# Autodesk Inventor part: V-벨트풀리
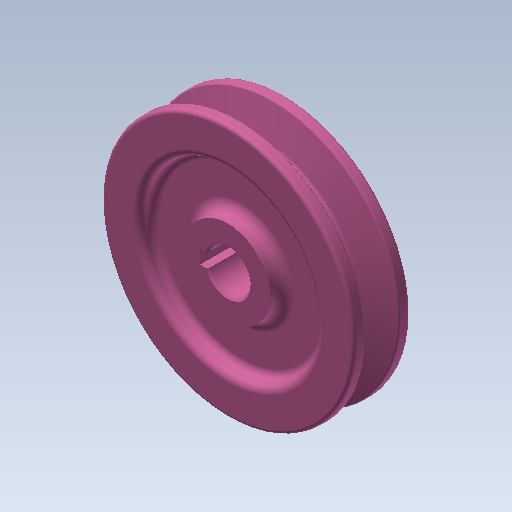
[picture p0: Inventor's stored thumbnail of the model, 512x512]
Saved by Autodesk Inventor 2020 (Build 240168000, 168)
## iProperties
CustomPartVersion: 1
Created: 2015-12
Part Number: V-벨트풀리
Material: 강철, 연강
Document SubType Name: Modeling
Designer: mdu
Density: 7.86 g/cm^3
Appearance: 분홍색
Author: mdu
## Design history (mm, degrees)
sketch "주 스케치"
  geometry: L1 (0, 16)-(35.7, 16); L2 (35.7, 16)-(35.7, 12.825); L3 (35.7, 12.825)-(26.7, 10.074); L4 (26.7, 10.074)-(26.7, 5.926); L5 (26.7, 5.926)-(35.7, 3.175); L6 (35.7, 3.175)-(35.7, 0); L7 (35.7, 0)-(0, 0); L8 (33, 12)-(33, 4); L9 (26.7, 8)-(33, 8); L10 (35.7, 12.825)-(35.7, 3.175); L11 (0, -3.2)-(0, 19.2) reference; L12 (0, 0)-(0, 16)
  constraints: 22 end point, 5 perpendicular, 2 collinear, 2 midpoint, 2 point on line, 1 parallel
  dimensions: "d0" = 8 distance of L8.start L8.end (= da_Bw); "d1" = 34 deg angle of L3 L5 (= da_Alfa); "d2" = 2.7 distance between parallel lines of L2 L8 (= da_c); "d6" = 16 distance between parallel lines of L7 L1 (computed from d5, da_ng, da_Sg); "d21" = 66 diameter of L8 L11; "d25" = 9 distance between parallel lines of L4 L10 (= da_Hd); "d27" = 8 distance between parallel lines of L7 L9 (= da_Se)
node "벨트 평면"
revolve "본체" stored, may be unused: angle "d7" = 90 deg
revolve "그루브" stored, may be unused: angle "d15" = 90 deg
feature "허브 키홈"
fillet "모깎기3" dims "d28" = 0.5, "d29" = 1, "d30" = 1
sketch "스케치2"
  geometry: C1 r 12 at (0, 0); C2 r 25 at (0, 0); 1 further point
  constraints: 2 centre point, 2 coincident
  dimensions: "d31" = 24 diameter of C1; "d32" = 50 diameter of C2
extrude "돌출1" cut sketch "스케치2" distance "d33" = 4; taper "d34" = 0 deg
node "작업 평면2"
fillet "모깎기4" dims "d35" = 3, "d39" = 2
chamfer "모따기1" distance "d36" = 0.5; stored, may be unused: second distance "d37" = 2, angle "d38" = 45 deg
body "Solid1"
pattern_linear "그루브 패턴" dims "d18" = 12 (= da_Sg)
mirror "대칭1"
other parameters: "d5" = 8 (= da_Se), "da_Bw" = 8 [user parameter; used in 1 equation term], "da_Alfa" = 34 deg [user parameter; used in 1 equation term], "da_c" = 2.7 [user parameter; used in 1 equation term], "da_Dw" = 64 [user parameter], "da_Hd" = 9 (computed from d2) [user parameter; used in 1 equation term], "da_Se" = 8 [user parameter; used in 2 equation terms], "da_Sg" = 12 [user parameter; used in 2 equation terms], "da_r1" = 0 [user parameter], "da_r2" = 0 [user parameter], "d24" = 0, "d26" = 0
